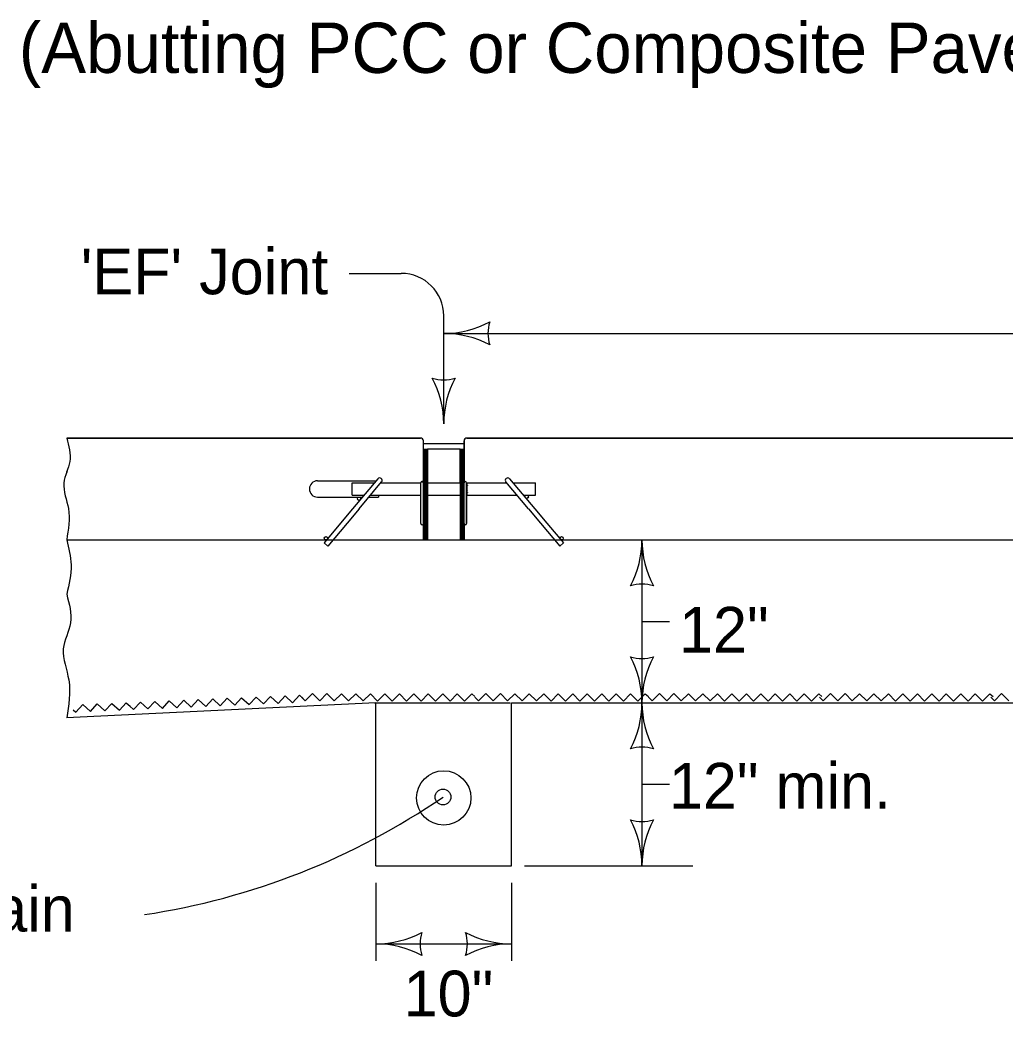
# Model space of a CAD drawing. Extents: x -2135039 to -2120895, y -2139150 to -2136566.
# Drawn here: x -2126862.4 to -2126431.3, y -2137933.2 to -2137497 of the extents above; entities that cross this region are included whole.
import ezdxf

# ---------------------------------------------------------------- set-up
doc = ezdxf.new("R2010")
doc.units = 0
for name, color, linetype in [('dsnStdLabel', 7, 'Continuous'), ('dsnStdLineWork', 7, 'Continuous'), ('Level 2', 7, 'Continuous')]:
    doc.layers.add(name, color=color, linetype=linetype)

msp = doc.modelspace()

# ---------------------------------------------------------------- linework, layer by layer
at = {"layer": 'dsnStdLabel'}
for p, q in [((-2126718.28, -2137607.91), (-2126695.5, -2137607.91)), ((-2126676.93, -2137641.4), (-2126676.93, -2137626.47)), ((-2126676.93, -2137634.17), (-2126262.05, -2137634.17)), ((-2126676.93, -2137673.79), (-2126676.93, -2137641.4)), ((-2126590.19, -2137724.48), (-2126590.19, -2137795.76)), ((-2126590.19, -2137760.12), (-2126578.07, -2137760.12)), ((-2126590.19, -2137795.76), (-2126590.19, -2137867.04)), ((-2126590.19, -2137831.4), (-2126578.07, -2137831.4)), ((-2126706.63, -2137874.47), (-2126706.63, -2137908.62)), ((-2126647.23, -2137874.47), (-2126647.23, -2137908.62)), ((-2126706.63, -2137901.2), (-2126647.23, -2137901.2))]:
    msp.add_line(p, q, dxfattribs=at)
msp.add_circle((-2126677.24, -2137836.95), 3.46, dxfattribs=at)
for centre, radius, start, end in [((-2126695.49, -2137626.47), 18.56, 0, 90), ((-2126676.93, -2137591.42), 42.75, 270, 298.0725), ((-2126641.09, -2137634.17), 16.51, 162.2666, 197.7334), ((-2126676.93, -2137676.92), 42.75, 61.9275, 90), ((-2126676.93, -2137637.95), 16.51, 252.2666, 287.7333), ((-2126719.68, -2137673.79), 42.75, 360, 28.0725), ((-2126634.18, -2137673.79), 42.75, 151.9275, 180), ((-2126632.94, -2137724.48), 42.75, 331.9275, 360), ((-2126632.94, -2137724.48), 42.75, 331.9275, 360), ((-2126547.44, -2137724.48), 42.75, 180, 208.0725), ((-2126547.44, -2137724.48), 42.75, 180, 208.0725), ((-2126590.19, -2137760.33), 16.51, 72.2666, 107.7334), ((-2126590.19, -2137760.33), 16.51, 72.2666, 107.7334), ((-2126590.19, -2137759.92), 16.51, 252.2666, 287.7333), ((-2126632.94, -2137795.76), 42.75, 360, 28.0725), ((-2126590.19, -2137759.92), 16.51, 252.2666, 287.7333), ((-2126632.94, -2137795.76), 42.75, 360, 28.0725), ((-2126547.44, -2137795.76), 42.75, 151.9275, 180), ((-2126547.44, -2137795.76), 42.75, 151.9275, 180), ((-2126632.94, -2137795.76), 42.75, 331.9275, 360), ((-2126632.94, -2137795.76), 42.75, 331.9275, 360), ((-2126547.44, -2137795.76), 42.75, 180, 208.0725), ((-2126547.44, -2137795.76), 42.75, 180, 208.0725), ((-2126590.19, -2137831.61), 16.51, 72.2666, 107.7334), ((-2126590.19, -2137831.61), 16.51, 72.2666, 107.7334), ((-2126854.87, -2137577.54), 314.4, 278.602, 304.4007), ((-2126590.19, -2137831.2), 16.51, 252.2666, 287.7333), ((-2126632.94, -2137867.04), 42.75, 360, 28.0725), ((-2126590.19, -2137831.2), 16.51, 252.2666, 287.7333), ((-2126632.94, -2137867.04), 42.75, 360, 28.0725), ((-2126547.44, -2137867.04), 42.75, 151.9275, 180), ((-2126547.44, -2137867.04), 42.75, 151.9275, 180), ((-2126706.63, -2137858.45), 42.75, 270, 298.0725), ((-2126706.63, -2137858.45), 42.75, 270, 298.0725), ((-2126670.79, -2137901.2), 16.51, 162.2666, 197.7334), ((-2126670.79, -2137901.2), 16.51, 162.2666, 197.7334), ((-2126683.08, -2137901.2), 16.51, 342.2666, 17.7333), ((-2126647.23, -2137858.45), 42.75, 241.9275, 270), ((-2126683.08, -2137901.2), 16.51, 342.2666, 17.7333), ((-2126647.23, -2137858.45), 42.75, 241.9275, 270), ((-2126706.63, -2137943.95), 42.75, 61.9275, 90), ((-2126706.63, -2137943.95), 42.75, 61.9275, 90), ((-2126647.23, -2137943.95), 42.75, 90, 118.0725), ((-2126647.23, -2137943.95), 42.75, 90, 118.0725)]:
    msp.add_arc(centre, radius, start, end, dxfattribs=at)
at = {"layer": 'dsnStdLineWork'}
for p, q in [((-2126841.93, -2137679.93), (-2126687.09, -2137679.93)), ((-2126685.84, -2137710.94), (-2126685.84, -2137681.19)), ((-2126668.02, -2137710.94), (-2126668.02, -2137681.19)), ((-2126666.77, -2137679.93), (-2125750.29, -2137679.93)), ((-2126685.84, -2137682.34), (-2126668.02, -2137682.34)), ((-2126685.84, -2137684.75), (-2126684.06, -2137684.75)), ((-2126685.66, -2137684.75), (-2126685.66, -2137710.94)), ((-2126685.49, -2137684.75), (-2126685.49, -2137710.94)), ((-2126685.31, -2137684.75), (-2126685.31, -2137710.94)), ((-2126685.13, -2137684.75), (-2126685.13, -2137710.94)), ((-2126684.95, -2137684.75), (-2126684.95, -2137710.94)), ((-2126684.77, -2137684.75), (-2126684.77, -2137710.94)), ((-2126684.59, -2137684.75), (-2126684.59, -2137710.94)), ((-2126684.42, -2137684.75), (-2126684.42, -2137710.94)), ((-2126684.24, -2137684.75), (-2126684.24, -2137710.94)), ((-2126669.8, -2137684.75), (-2126684.06, -2137684.75)), ((-2126684.06, -2137684.75), (-2126684.06, -2137699.54)), ((-2126669.8, -2137699.54), (-2126669.8, -2137684.75)), ((-2126669.8, -2137684.75), (-2126668.02, -2137684.75)), ((-2126669.63, -2137684.75), (-2126669.63, -2137710.94)), ((-2126669.45, -2137684.75), (-2126669.45, -2137710.94)), ((-2126669.27, -2137684.75), (-2126669.27, -2137710.94)), ((-2126669.09, -2137684.75), (-2126669.09, -2137710.94)), ((-2126668.91, -2137684.75), (-2126668.91, -2137710.94)), ((-2126668.74, -2137684.75), (-2126668.74, -2137710.94)), ((-2126668.56, -2137684.75), (-2126668.56, -2137710.94)), ((-2126668.38, -2137684.75), (-2126668.38, -2137710.94)), ((-2126668.2, -2137684.75), (-2126668.2, -2137710.94)), ((-2126732.17, -2137698.65), (-2126706.48, -2137698.65)), ((-2126705.75, -2137697.78), (-2126716.79, -2137710.94)), ((-2126648.11, -2137697.78), (-2126637.07, -2137710.94)), ((-2126717.03, -2137704.88), (-2126717.03, -2137699.54)), ((-2126717.03, -2137699.54), (-2126707.23, -2137699.54)), ((-2126714.01, -2137710.94), (-2126704.11, -2137699.16)), ((-2126704.43, -2137699.54), (-2126686.91, -2137699.54)), ((-2126686.91, -2137717.36), (-2126686.91, -2137699.54)), ((-2126684.06, -2137699.54), (-2126684.06, -2137704.88)), ((-2126684.06, -2137699.54), (-2126669.8, -2137699.54)), ((-2126669.8, -2137699.54), (-2126669.8, -2137704.88)), ((-2126666.95, -2137717.36), (-2126666.95, -2137699.54)), ((-2126666.95, -2137699.54), (-2126649.43, -2137699.54)), ((-2126666.95, -2137700.25), (-2126666.95, -2137700.25)), ((-2126639.86, -2137710.94), (-2126649.75, -2137699.16)), ((-2126646.64, -2137699.54), (-2126636.84, -2137699.54)), ((-2126636.84, -2137704.88), (-2126636.84, -2137699.54)), ((-2126732.17, -2137705.78), (-2126712.46, -2137705.78)), ((-2126717.03, -2137704.88), (-2126711.71, -2137704.88)), ((-2126709.66, -2137705.78), (-2126705.44, -2137705.78)), ((-2126708.92, -2137704.88), (-2126686.91, -2137704.88)), ((-2126705.44, -2137704.88), (-2126705.44, -2137705.78)), ((-2126684.06, -2137704.88), (-2126669.8, -2137704.88)), ((-2126684.06, -2137704.88), (-2126684.06, -2137710.94)), ((-2126669.8, -2137704.88), (-2126669.8, -2137710.94)), ((-2126666.95, -2137704.88), (-2126644.94, -2137704.88)), ((-2126642.16, -2137704.88), (-2126636.84, -2137704.88)), ((-2126716.79, -2137710.94), (-2126722.05, -2137717.21)), ((-2126714.01, -2137710.94), (-2126719.26, -2137717.21)), ((-2126685.84, -2137717.21), (-2126685.84, -2137710.94)), ((-2126685.66, -2137710.94), (-2126685.66, -2137717.21)), ((-2126685.49, -2137710.94), (-2126685.49, -2137717.21)), ((-2126685.31, -2137710.94), (-2126685.31, -2137717.21)), ((-2126685.13, -2137710.94), (-2126685.13, -2137717.21)), ((-2126684.95, -2137710.94), (-2126684.95, -2137717.21)), ((-2126684.77, -2137710.94), (-2126684.77, -2137717.21)), ((-2126684.59, -2137710.94), (-2126684.59, -2137717.21)), ((-2126684.42, -2137710.94), (-2126684.42, -2137717.21)), ((-2126684.24, -2137710.94), (-2126684.24, -2137717.21)), ((-2126684.06, -2137710.94), (-2126684.06, -2137717.21)), ((-2126669.8, -2137710.94), (-2126669.8, -2137717.21)), ((-2126669.63, -2137710.94), (-2126669.63, -2137717.21)), ((-2126669.45, -2137710.94), (-2126669.45, -2137717.21)), ((-2126669.27, -2137710.94), (-2126669.27, -2137717.21)), ((-2126669.09, -2137710.94), (-2126669.09, -2137717.21)), ((-2126668.91, -2137710.94), (-2126668.91, -2137717.21)), ((-2126668.74, -2137710.94), (-2126668.74, -2137717.21)), ((-2126668.56, -2137710.94), (-2126668.56, -2137717.21)), ((-2126668.38, -2137710.94), (-2126668.38, -2137717.21)), ((-2126668.2, -2137710.94), (-2126668.2, -2137717.21)), ((-2126668.02, -2137717.21), (-2126668.02, -2137710.94)), ((-2126639.86, -2137710.94), (-2126634.6, -2137717.21)), ((-2126637.07, -2137710.94), (-2126631.81, -2137717.21)), ((-2126722.05, -2137717.21), (-2126729.3, -2137725.84)), ((-2126719.26, -2137717.21), (-2126727.66, -2137727.22)), ((-2126685.84, -2137724.48), (-2126685.84, -2137717.21)), ((-2126685.66, -2137717.21), (-2126685.66, -2137724.48)), ((-2126685.49, -2137717.21), (-2126685.49, -2137724.48)), ((-2126685.31, -2137717.21), (-2126685.31, -2137724.48)), ((-2126685.13, -2137717.21), (-2126685.13, -2137724.48)), ((-2126684.95, -2137717.21), (-2126684.95, -2137724.48)), ((-2126684.77, -2137717.21), (-2126684.77, -2137724.48)), ((-2126684.59, -2137717.21), (-2126684.59, -2137724.48)), ((-2126684.42, -2137717.21), (-2126684.42, -2137724.48)), ((-2126684.24, -2137717.21), (-2126684.24, -2137724.48)), ((-2126684.06, -2137717.21), (-2126684.06, -2137724.48)), ((-2126669.8, -2137717.21), (-2126669.8, -2137724.48)), ((-2126669.63, -2137717.21), (-2126669.63, -2137724.48)), ((-2126669.45, -2137717.21), (-2126669.45, -2137724.48)), ((-2126669.27, -2137717.21), (-2126669.27, -2137724.48)), ((-2126669.09, -2137717.21), (-2126669.09, -2137724.48)), ((-2126668.91, -2137717.21), (-2126668.91, -2137724.48)), ((-2126668.74, -2137717.21), (-2126668.74, -2137724.48)), ((-2126668.56, -2137717.21), (-2126668.56, -2137724.48)), ((-2126668.38, -2137717.21), (-2126668.38, -2137724.48)), ((-2126668.2, -2137717.21), (-2126668.2, -2137724.48)), ((-2126668.02, -2137724.48), (-2126668.02, -2137717.21)), ((-2126634.6, -2137717.21), (-2126626.2, -2137727.22)), ((-2126631.81, -2137717.21), (-2126624.56, -2137725.84)), ((-2126841.93, -2137724.48), (-2126728.16, -2137724.48)), ((-2126725.37, -2137724.48), (-2126684.06, -2137724.48)), ((-2126684.06, -2137724.48), (-2126669.8, -2137724.48)), ((-2126669.8, -2137724.48), (-2126628.49, -2137724.48)), ((-2126625.71, -2137724.48), (-2125750.29, -2137724.48)), ((-2126727.66, -2137727.22), (-2126729.3, -2137725.84)), ((-2126626.2, -2137727.22), (-2126624.56, -2137725.84)), ((-2126706.63, -2137795.76), (-2126841.94, -2137802.32)), ((-2126707.25, -2137795.76), (-2126647.85, -2137795.76)), ((-2126706.63, -2137867.04), (-2126706.63, -2137795.76)), ((-2126647.23, -2137867.04), (-2126647.23, -2137795.76)), ((-2126647.23, -2137795.76), (-2125750.29, -2137795.76)), ((-2126706.63, -2137867.04), (-2126647.23, -2137867.04)), ((-2126641.66, -2137867.04), (-2126567.86, -2137867.04))]:
    msp.add_line(p, q, dxfattribs=at)
for points in [[(-2126814.36, -2137797.21), (-2126812.72, -2137798.72), (-2126809.69, -2137795.43), (-2126806.39, -2137798.45), (-2126803.36, -2137795.14), (-2126800.06, -2137798.17), (-2126797.03, -2137794.87), (-2126793.73, -2137797.9), (-2126790.7, -2137794.6), (-2126787.4, -2137797.63), (-2126784.36, -2137794.32), (-2126781.07, -2137797.36), (-2126778.04, -2137794.05), (-2126774.73, -2137797.08), (-2126771.71, -2137793.78), (-2126768.41, -2137796.8), (-2126765.38, -2137793.51), (-2126762.08, -2137796.53), (-2126759.05, -2137793.23), (-2126755.75, -2137796.26), (-2126752.72, -2137792.95), (-2126749.42, -2137795.98), (-2126746.39, -2137792.68), (-2126743.08, -2137795.71), (-2126740.06, -2137792.42), (-2126738.41, -2137793.92)], [(-2126739.12, -2137793.28), (-2126737.54, -2137794.87), (-2126734.36, -2137791.71), (-2126731.21, -2137794.89), (-2126728.03, -2137791.73), (-2126724.87, -2137794.91), (-2126721.7, -2137791.75), (-2126718.54, -2137794.93), (-2126715.35, -2137791.76), (-2126712.2, -2137794.94), (-2126709.02, -2137791.78), (-2126705.86, -2137794.96), (-2126702.68, -2137791.8), (-2126699.53, -2137794.97), (-2126696.35, -2137791.81), (-2126693.19, -2137794.99), (-2126690.02, -2137791.83), (-2126686.86, -2137795.01), (-2126683.68, -2137791.84), (-2126680.52, -2137795.02), (-2126677.34, -2137791.86), (-2126674.18, -2137795.04), (-2126671.01, -2137791.88), (-2126667.85, -2137795.06), (-2126664.67, -2137791.89), (-2126663.25, -2137793.03)], [(-2126663.25, -2137793.28), (-2126661.68, -2137794.87), (-2126658.49, -2137791.71), (-2126655.34, -2137794.89), (-2126652.16, -2137791.73), (-2126649, -2137794.91), (-2126645.83, -2137791.75), (-2126642.67, -2137794.93), (-2126639.48, -2137791.76), (-2126636.33, -2137794.94), (-2126633.15, -2137791.78), (-2126629.99, -2137794.96), (-2126626.81, -2137791.8), (-2126623.66, -2137794.97), (-2126620.48, -2137791.81), (-2126617.32, -2137794.99), (-2126614.15, -2137791.83), (-2126610.99, -2137795.01), (-2126607.81, -2137791.84), (-2126604.65, -2137795.02), (-2126601.47, -2137791.86), (-2126598.32, -2137795.04), (-2126595.14, -2137791.88), (-2126591.98, -2137795.06), (-2126588.8, -2137791.89), (-2126587.38, -2137793.03)], [(-2126587.28, -2137793.28), (-2126585.71, -2137794.87), (-2126582.52, -2137791.71), (-2126579.37, -2137794.89), (-2126576.19, -2137791.73), (-2126573.03, -2137794.91), (-2126569.86, -2137791.75), (-2126566.7, -2137794.93), (-2126563.52, -2137791.76), (-2126560.36, -2137794.94), (-2126557.18, -2137791.78), (-2126554.02, -2137794.96), (-2126550.84, -2137791.8), (-2126547.69, -2137794.97), (-2126544.51, -2137791.81), (-2126541.35, -2137794.99), (-2126538.18, -2137791.83), (-2126535.02, -2137795.01), (-2126531.84, -2137791.84), (-2126528.68, -2137795.02), (-2126525.5, -2137791.86), (-2126522.35, -2137795.04), (-2126519.17, -2137791.88), (-2126516.01, -2137795.06), (-2126512.84, -2137791.89), (-2126511.41, -2137793.03)], [(-2126512.44, -2137793.28), (-2126510.86, -2137794.87), (-2126507.68, -2137791.71), (-2126504.53, -2137794.89), (-2126501.34, -2137791.73), (-2126498.19, -2137794.91), (-2126495.02, -2137791.75), (-2126491.86, -2137794.93), (-2126488.67, -2137791.76), (-2126485.52, -2137794.94), (-2126482.34, -2137791.78), (-2126479.18, -2137794.96), (-2126476, -2137791.8), (-2126472.85, -2137794.97), (-2126469.67, -2137791.81), (-2126466.51, -2137794.99), (-2126463.34, -2137791.83), (-2126460.18, -2137795.01), (-2126457, -2137791.84), (-2126453.84, -2137795.02), (-2126450.66, -2137791.86), (-2126447.5, -2137795.04), (-2126444.33, -2137791.88), (-2126441.17, -2137795.06), (-2126437.99, -2137791.89), (-2126436.57, -2137793.03)], [(-2126437.55, -2137793.28), (-2126435.97, -2137794.87), (-2126432.79, -2137791.71), (-2126429.64, -2137794.89)], [(-2126839.04, -2137798.78), (-2126837.88, -2137799.84), (-2126834.85, -2137796.54), (-2126831.55, -2137799.57), (-2126828.52, -2137796.26), (-2126825.22, -2137799.29), (-2126822.19, -2137795.99), (-2126818.88, -2137799.02), (-2126815.86, -2137795.72), (-2126814.21, -2137797.23)]]:
    msp.add_lwpolyline(points, dxfattribs=at)
for centre, radius in [((-2126713.99, -2137706.49), 0.713), ((-2126640.62, -2137705.6), 0.713), ((-2126728.49, -2137723.77), 0.713), ((-2126625.37, -2137723.77), 0.713), ((-2126676.93, -2137837.34), 11.88)]:
    msp.add_circle(centre, radius, dxfattribs=at)
for centre, radius, start, end in [((-2126687.09, -2137681.18), 1.25, 0, 90), ((-2126666.77, -2137681.18), 1.25, 90, 180), ((-2126732.17, -2137702.21), 3.56, 90, 270), ((-2126704.93, -2137698.47), 1.07, 320.0037, 139.9964), ((-2126648.93, -2137698.47), 1.07, 40.0036, 219.9963), ((-2126686.38, -2137699.54), 0.535, 0, 180), ((-2126667.49, -2137699.54), 0.535, 0, 180), ((-2126686.38, -2137717.36), 0.535, 180, 0), ((-2126667.49, -2137717.36), 0.535, 180, 0)]:
    msp.add_arc(centre, radius, start, end, dxfattribs=at)
for points in [[(-2126841.93, -2137679.93), (-2126840.57, -2137690.23), (-2126843.15, -2137699.6), (-2126841.18, -2137710.79), (-2126841.93, -2137724.48)], [(-2126666.95, -2137699.89), (-2126666.86, -2137699.9), (-2126666.77, -2137699.89), (-2126666.7, -2137699.9), (-2126666.63, -2137699.89), (-2126666.57, -2137699.9), (-2126666.52, -2137699.9)], [(-2126666.95, -2137700.25), (-2126666.86, -2137700.26), (-2126666.77, -2137700.24), (-2126666.7, -2137700.26), (-2126666.63, -2137700.24), (-2126666.57, -2137700.26), (-2126666.52, -2137700.25)], [(-2126666.95, -2137700.61), (-2126666.86, -2137700.61), (-2126666.77, -2137700.6), (-2126666.7, -2137700.61), (-2126666.63, -2137700.6), (-2126666.57, -2137700.62), (-2126666.52, -2137700.61)], [(-2126666.95, -2137700.96), (-2126666.86, -2137700.97), (-2126666.77, -2137700.96), (-2126666.7, -2137700.97), (-2126666.63, -2137700.95), (-2126666.57, -2137700.97), (-2126666.52, -2137700.97)], [(-2126666.95, -2137701.32), (-2126666.86, -2137701.33), (-2126666.77, -2137701.31), (-2126666.7, -2137701.33), (-2126666.63, -2137701.31), (-2126666.57, -2137701.33), (-2126666.52, -2137701.32)], [(-2126666.95, -2137701.67), (-2126666.86, -2137701.68), (-2126666.77, -2137701.67), (-2126666.7, -2137701.68), (-2126666.63, -2137701.67), (-2126666.57, -2137701.69), (-2126666.52, -2137701.68)], [(-2126666.95, -2137702.03), (-2126666.86, -2137702.04), (-2126666.77, -2137702.03), (-2126666.7, -2137702.04), (-2126666.63, -2137702.02), (-2126666.57, -2137702.04), (-2126666.52, -2137702.03)], [(-2126666.95, -2137702.39), (-2126666.86, -2137702.4), (-2126666.77, -2137702.38), (-2126666.7, -2137702.4), (-2126666.63, -2137702.38), (-2126666.57, -2137702.4), (-2126666.52, -2137702.39)], [(-2126666.95, -2137702.74), (-2126666.86, -2137702.75), (-2126666.77, -2137702.74), (-2126666.7, -2137702.75), (-2126666.63, -2137702.74), (-2126666.57, -2137702.76), (-2126666.52, -2137702.75)], [(-2126666.95, -2137703.1), (-2126666.86, -2137703.11), (-2126666.77, -2137703.1), (-2126666.7, -2137703.11), (-2126666.63, -2137703.09), (-2126666.57, -2137703.11), (-2126666.52, -2137703.1)], [(-2126666.95, -2137703.46), (-2126666.86, -2137703.46), (-2126666.77, -2137703.45), (-2126666.7, -2137703.46), (-2126666.63, -2137703.45), (-2126666.57, -2137703.47), (-2126666.52, -2137703.46)], [(-2126666.95, -2137703.81), (-2126666.86, -2137703.82), (-2126666.77, -2137703.81), (-2126666.7, -2137703.82), (-2126666.63, -2137703.81), (-2126666.57, -2137703.83), (-2126666.52, -2137703.82)], [(-2126666.95, -2137704.17), (-2126666.86, -2137704.18), (-2126666.77, -2137704.17), (-2126666.7, -2137704.18), (-2126666.63, -2137704.16), (-2126666.57, -2137704.18), (-2126666.52, -2137704.17)], [(-2126666.95, -2137704.53), (-2126666.86, -2137704.53), (-2126666.77, -2137704.52), (-2126666.7, -2137704.53), (-2126666.63, -2137704.52), (-2126666.57, -2137704.54), (-2126666.52, -2137704.53)], [(-2126841.93, -2137724.48), (-2126839.97, -2137735.43), (-2126841.93, -2137748.24)], [(-2126841.93, -2137748.24), (-2126840.28, -2137760.76), (-2126843.4, -2137772.15), (-2126841.02, -2137785.75), (-2126841.93, -2137802.39)]]:
    msp.add_spline(points, degree=3, dxfattribs=at)
at = {"layer": 'Level 2'}
for p, q in [((-2126687.09, -2137679.93), (-2126841.93, -2137679.93)), ((-2126685.84, -2137699.5), (-2126685.84, -2137681.18)), ((-2126668.02, -2137681.18), (-2126668.02, -2137699.54)), ((-2125750.3, -2137679.94), (-2126666.77, -2137679.93)), ((-2126686.91, -2137717.35), (-2126686.91, -2137699.53)), ((-2126666.95, -2137699.54), (-2126666.95, -2137717.36)), ((-2126685.84, -2137724.48), (-2126685.84, -2137717.4)), ((-2126668.02, -2137717.36), (-2126668.02, -2137724.49)), ((-2126841.93, -2137724.48), (-2126725.37, -2137724.48)), ((-2126725.37, -2137724.48), (-2126685.84, -2137724.48)), ((-2126668.02, -2137724.49), (-2126625.71, -2137724.49)), ((-2126625.71, -2137724.49), (-2125750.3, -2137724.49))]:
    msp.add_line(p, q, dxfattribs=at)
for points in [[(-2126668.02, -2137699.54), (-2126668.02, -2137699.54)], [(-2126668.02, -2137717.36), (-2126668.02, -2137717.36)]]:
    msp.add_lwpolyline(points, dxfattribs=at)
for centre, radius, start, end in [((-2126687.09, -2137681.18), 1.25, 360, 90), ((-2126666.77, -2137681.18), 1.25, 90, 180), ((-2126686.37, -2137699.53), 0.535, 3.7252, 180), ((-2126667.49, -2137699.54), 0.535, 0, 180), ((-2126686.37, -2137717.35), 0.535, 180, 355.2519), ((-2126667.49, -2137717.36), 0.535, 180, 0)]:
    msp.add_arc(centre, radius, start, end, dxfattribs=at)
msp.add_spline([(-2126841.93, -2137679.93), (-2126840.57, -2137690.23), (-2126843.14, -2137699.6), (-2126841.18, -2137710.79), (-2126841.93, -2137724.48)], degree=3, dxfattribs=at)

# ---------------------------------------------------------------- texts
at = {"layer": 'dsnStdLabel'}
for s, p in [("'EF' Joint", (-2126835.77, -2137617.04)), ('12"', (-2126573.95, -2137773.78)), ('12" min.', (-2126578.41, -2137842.04)), ('4" Perforated Subdrain', (-2127109.55, -2137895.84)), ('10"', (-2126694.49, -2137932.92))]:
    msp.add_text(s, height=20, dxfattribs=at).set_placement(p)
at = {"layer": 'dsnStdLineWork'}
msp.add_text('(Abutting PCC or Composite Pavement)', height=22, dxfattribs=at).set_placement((-2126862.85, -2137520.22))

doc.saveas('drawing.dxf')
